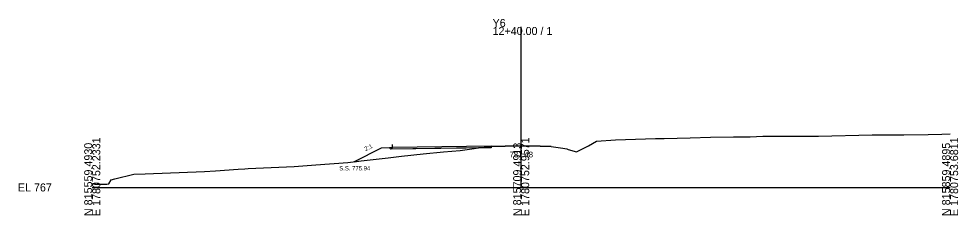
# Model space of a CAD drawing. Extents: x -26 to 1603, y -10 to 6024.
# Drawn here: x -25.7 to 302.8, y 2990.3 to 3058.9 of the extents above; entities that cross this region are included whole.
import ezdxf

# ---------------------------------------------------------------- set-up
doc = ezdxf.new("R2010")
doc.units = 0
for name, color, linetype in [('Exist Cross Section Cell', 7, 'Continuous'), ('Exist XS Center Line Elevation Label', 7, 'Continuous'), ('Exist XS Ground Line', 7, 'Continuous'), ('Prop XS Dump Level', 7, 'Continuous'), ('Prop XS Earthwork Shape', 7, 'Continuous'), ('Prop XS EOT Tick Mark', 7, 'Continuous'), ('Prop XS Finish Grade', 7, 'Continuous'), ('Prop XS Finish Grade Earthwork', 7, 'Continuous'), ('Prop XS Finish Grade Pavement', 7, 'Continuous'), ('Prop XS Pvmt Edge Slope', 7, 'Continuous'), ('Prop XS Side Slope Text', 7, 'Continuous'), ('Prop XS SS Elevation Text', 7, 'Continuous'), ('Prop XS Subgrade Earthwork', 7, 'Continuous')]:
    doc.layers.add(name, color=color, linetype=linetype)

msp = doc.modelspace()

# ---------------------------------------------------------------- linework, layer by layer
at = {"layer": 'Exist Cross Section Cell'}
for p, q in [((150, 3000), (150, 3056.03)), ((0, 3000), (150, 3000)), ((150, 3000), (300, 3000))]:
    msp.add_line(p, q, dxfattribs=at)
at = {"layer": 'Exist XS Ground Line'}
for p, q in [((173.6, 3014.5), (176.32, 3016.19)), ((176.32, 3016.19), (183.03, 3016.6)), ((183.03, 3016.6), (196.96, 3017.09)), ((196.96, 3017.09), (200.01, 3017.13)), ((200.01, 3017.13), (209.05, 3017.3)), ((209.05, 3017.3), (216.22, 3017.55)), ((216.22, 3017.55), (224.25, 3017.68)), ((224.25, 3017.68), (230.08, 3017.72)), ((230.08, 3017.72), (234.54, 3017.85)), ((234.54, 3017.85), (248.32, 3017.92)), ((248.32, 3017.92), (251.45, 3017.9)), ((251.45, 3017.9), (253.94, 3017.86)), ((253.94, 3017.86), (272.8, 3018.33)), ((272.8, 3018.33), (273.25, 3018.34)), ((273.25, 3018.34), (283.77, 3018.42)), ((283.77, 3018.42), (292.37, 3018.49)), ((292.37, 3018.49), (297.11, 3018.61)), ((297.11, 3018.61), (300, 3018.68)), ((122.8, 3012.39), (128.71, 3012.92)), ((128.71, 3012.92), (132.74, 3013.43)), ((132.74, 3013.43), (135.79, 3013.91)), ((135.79, 3013.91), (139.48, 3014.31)), ((139.48, 3014.31), (144.35, 3014.38)), ((144.35, 3014.38), (150.03, 3014.48)), ((150.03, 3014.48), (156.64, 3014.37)), ((156.64, 3014.37), (160.46, 3014.3)), ((160.46, 3014.3), (164.62, 3013.68)), ((164.62, 3013.68), (166.02, 3013.5)), ((166.02, 3013.5), (166.43, 3013.28)), ((166.43, 3013.28), (169.38, 3012.43)), ((169.38, 3012.43), (170.28, 3012.91)), ((170.28, 3012.91), (173.6, 3014.5)), ((94.03, 3009.23), (103.47, 3010.31)), ((103.47, 3010.31), (108.18, 3010.9)), ((108.18, 3010.9), (115.73, 3011.72)), ((115.73, 3011.72), (122.8, 3012.39)), ((43.1, 3005.8), (51.04, 3006.38)), ((51.04, 3006.38), (53.37, 3006.54)), ((53.37, 3006.54), (54.56, 3006.55)), ((54.56, 3006.55), (70.56, 3007.34)), ((70.56, 3007.34), (78.15, 3007.89)), ((78.15, 3007.89), (89.39, 3008.69)), ((89.39, 3008.69), (94.03, 3009.23)), ((6.66, 3002.65), (7.89, 3003.01)), ((7.89, 3003.01), (14.5, 3004.58)), ((14.5, 3004.58), (18.54, 3004.7)), ((18.54, 3004.7), (39.21, 3005.55)), ((39.21, 3005.55), (43.1, 3005.8)), ((0, 3001.36), (0.91, 3001.11)), ((0.91, 3001.11), (5.06, 3001.19)), ((5.06, 3001.19), (5.76, 3001.22)), ((5.76, 3001.22), (6.66, 3002.65))]:
    msp.add_line(p, q, dxfattribs=at)
at = {"layer": 'Prop XS Earthwork Shape'}
for points in [[(135.03, 3013.79), (104.41, 3013.36), (103.9, 3013.87), (101, 3013.65), (91.58, 3008.94), (94.03, 3009.23), (103.47, 3010.31), (108.18, 3010.9), (115.73, 3011.72), (122.8, 3012.39), (128.71, 3012.92), (132.74, 3013.43)], [(135.03, 3013.79), (135.79, 3013.91), (139.48, 3014.31), (139.48, 3013.86)]]:
    msp.add_lwpolyline(points, close=True, dxfattribs=at)
at = {"layer": 'Prop XS EOT Tick Mark'}
msp.add_line((105, 3013.95), (105, 3014.95), dxfattribs=at)
msp.add_line((105, 3013.95), (105, 3014.95), dxfattribs=at)
at = {"layer": 'Prop XS Finish Grade'}
msp.add_line((105, 3013.95), (103.9, 3013.87), dxfattribs=at)
at = {"layer": 'Prop XS Finish Grade Earthwork'}
for p, q in [((101, 3013.65), (91.58, 3008.94)), ((101, 3013.65), (91.58, 3008.94)), ((103.9, 3013.87), (101, 3013.65))]:
    msp.add_line(p, q, dxfattribs=at)
at = {"layer": 'Prop XS Finish Grade Pavement'}
for p, q in [((139.48, 3014.44), (105, 3013.95)), ((139.48, 3014.44), (105, 3013.95)), ((139.48, 3014.44), (144.35, 3014.51)), ((139.48, 3014.44), (139.49, 3014.31)), ((139.48, 3014.44), (139.49, 3014.31)), ((144.35, 3014.51), (150.03, 3014.61)), ((150.03, 3014.61), (156.65, 3014.49)), ((156.65, 3014.49), (160.46, 3014.43))]:
    msp.add_line(p, q, dxfattribs=at)
at = {"layer": 'Prop XS Pvmt Edge Slope'}
msp.add_line((105, 3013.95), (104.41, 3013.36), dxfattribs=at)
at = {"layer": 'Prop XS Subgrade Earthwork'}
for p, q in [((104.41, 3013.36), (103.9, 3013.87)), ((139.48, 3013.86), (104.41, 3013.36)), ((139.48, 3013.86), (139.48, 3014.31))]:
    msp.add_line(p, q, dxfattribs=at)

# ---------------------------------------------------------------- texts
at = {"layer": 'Exist Cross Section Cell'}
for s, p in [('Y6', (140, 3056.03)), ('12+40.00 / 1', (140, 3053.23)), ('EL 767', (-26, 2998.6))]:
    msp.add_text(s, height=2.8, dxfattribs=at).set_placement(p)
for s, p in [('E 1780752.2331', (2.8, 2990)), ('E 1780752.9571', (152.8, 2990)), ('E 1780753.6811', (302.8, 2990)), ('N 815559.4930', (0, 2990)), ('N 815709.4913', (150, 2990)), ('N 815859.4895', (300, 2990))]:
    msp.add_text(s, height=2.8, rotation=90, dxfattribs=at).set_placement(p)
at = {"layer": 'Exist XS Center Line Elevation Label'}
msp.add_text('781.48', height=2, dxfattribs=at).set_placement((145.96, 3010.48))
at = {"layer": 'Prop XS Dump Level'}
for s, height, p in [('Case1', 0.04, (101, 3013.61)), ('Case1', 0.04, (101, 3013.61)), ('Eop', 0.3, (139.48, 3014.01)), ('Eop', 0.3, (139.48, 3014.01))]:
    msp.add_text(s, height=height, dxfattribs=at).set_placement(p)
at = {"layer": 'Prop XS Side Slope Text'}
msp.add_text('2:1', height=1.5, rotation=26.5651, dxfattribs=at).set_placement((95.62, 3012.64))
msp.add_text('2:1', height=1.5, rotation=26.5651, dxfattribs=at).set_placement((95.62, 3012.64))
at = {"layer": 'Prop XS SS Elevation Text'}
msp.add_text('S.S. 775.94', height=1.5, dxfattribs=at).set_placement((86.39, 3005.94))
msp.add_text('S.S. 775.94', height=1.5, dxfattribs=at).set_placement((86.39, 3005.94))

doc.saveas('drawing.dxf')
